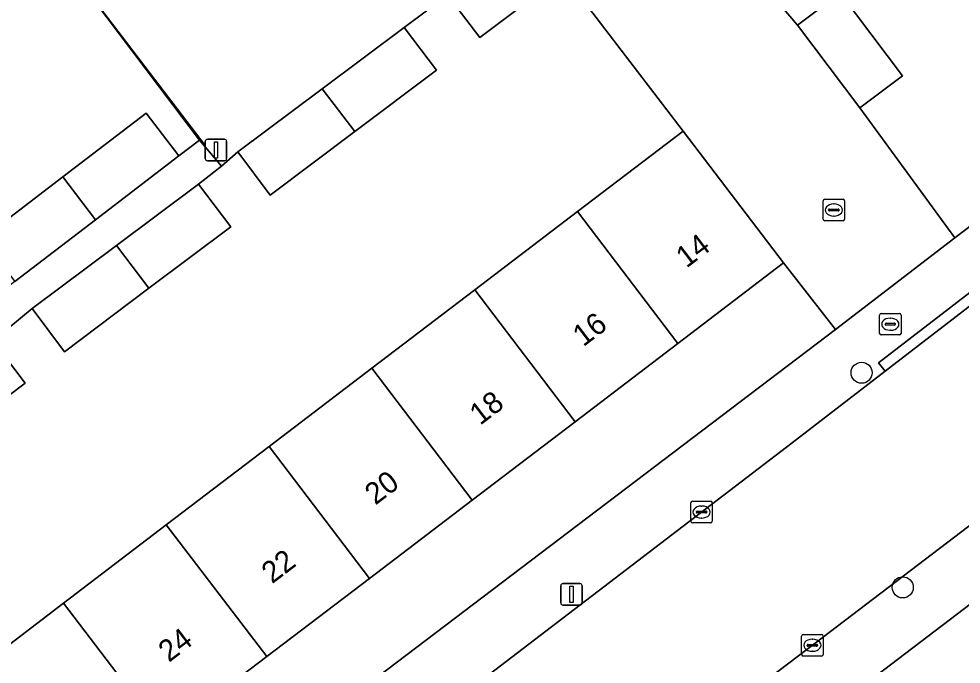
# Model space of a CAD drawing. Extents: x 160030 to 160839, y 385325 to 386450.
# Drawn here: x 160363.46 to 160407.21, y 385760.66 to 385790.62 of the extents above; entities that cross this region are included whole.
import ezdxf

# ---------------------------------------------------------------- set-up
doc = ezdxf.new("R2010")
doc.units = 0
for name, color, linetype in [('IMGEO_Boom', 7, 'Continuous'), ('IMGEO_Brandkraan', 7, 'Continuous'), ('IMGEO_Erf', 7, 'Continuous'), ('IMGEO_Kolk', 7, 'Continuous'), ('IMGEO_Lichtmast', 7, 'Continuous'), ('IMGEO_Muur', 7, 'Continuous'), ('IMGEO_Pand', 7, 'Continuous'), ('IMGEO_Pand_nummerreeks', 7, 'Continuous'), ('IMGEO_Rijbaan_lokaal_gesloten', 7, 'Continuous'), ('IMGEO_Rijbaan_lokaal_open', 7, 'Continuous'), ('IMGEO_Voetpad_open', 7, 'Continuous')]:
    doc.layers.add(name, color=color, linetype=linetype)

msp = doc.modelspace()

# ---------------------------------------------------------------- linework, layer by layer
at = {"layer": 'IMGEO_Boom'}
for centre in [(160402.589, 385774.189), (160404.501, 385764.222)]:
    msp.add_circle(centre, 0.489, dxfattribs=at)
at = {"layer": 'IMGEO_Brandkraan'}
for p, q in [((160403.423, 385776.017), (160403.423, 385776.869)), ((160403.498, 385776.943), (160404.35, 385776.943)), ((160403.911, 385776.723), (160403.936, 385776.723)), ((160404.424, 385776.869), (160404.424, 385776.017)), ((160403.682, 385776.437), (160403.682, 385776.449)), ((160404.12, 385776.4), (160403.722, 385776.4)), ((160403.725, 385776.486), (160404.123, 385776.486)), ((160404.166, 385776.449), (160404.166, 385776.437)), ((160404.35, 385775.943), (160403.498, 385775.943)), ((160403.934, 385776.163), (160403.909, 385776.163))]:
    msp.add_line(p, q, dxfattribs=at)
for points in [[(160403.423, 385776.017), (160403.423, 385776.869)], [(160403.498, 385776.943), (160404.35, 385776.943)], [(160404.424, 385776.869), (160404.424, 385776.017)], [(160404.35, 385775.943), (160403.498, 385775.943)]]:
    msp.add_lwpolyline(points, dxfattribs=at)
for centre, radius, start, end in [((160403.5, 385776.867), 0.0765, 91.552, 178.448), ((160403.5, 385776.867), 0.0765, 91.552, 178.448), ((160404.348, 385776.867), 0.0765, 1.552, 88.448), ((160404.348, 385776.867), 0.0765, 1.552, 88.448), ((160403.722, 385776.446), 0.0403, 85.8775, 175.7526), ((160403.719, 385776.436), 0.0366, 178.938, 274.7102), ((160404.123, 385776.443), 0.043, 264.8664, 352.4533), ((160404.127, 385776.448), 0.0386, 1.7309, 96.639), ((160403.5, 385776.019), 0.0765, 181.552, 268.448), ((160403.5, 385776.019), 0.0765, 181.552, 268.448), ((160404.348, 385776.019), 0.0765, 271.552, 358.448), ((160404.348, 385776.019), 0.0765, 271.552, 358.448)]:
    msp.add_arc(centre, radius, start, end, dxfattribs=at)
for centre, major_axis, ratio, start_param, end_param in [((160403.91, 385776.443), (-0.387, 0.002), 0.722429, 4.712389, 7.853982), ((160403.935, 385776.443), (-0.39, 0.002), 0.717154, 1.570796, 4.712389)]:
    msp.add_ellipse(centre, major_axis=major_axis, ratio=ratio, start_param=start_param, end_param=end_param, dxfattribs=at)
at = {"layer": 'IMGEO_Erf'}
for points in [[(160379.773, 385820.336), (160382.575, 385816.635), (160385.586, 385812.658), (160383.578, 385811.138), (160385.012, 385809.268), (160387.001, 385810.774), (160389.812, 385807.062), (160392.815, 385803.096), (160390.826, 385801.59), (160392.329, 385799.662), (160394.322, 385801.189), (160397.118, 385797.54), (160400.181, 385793.542), (160398.188, 385792.015), (160399.617, 385790.332), (160401.599, 385791.824), (160404.494, 385787.977), (160402.512, 385786.485), (160406.915, 385780.456), (160424.865, 385794.109)], [(160361.761, 385780.417), (160365.508, 385783.286), (160369.374, 385786.247), (160370.893, 385784.263), (160371.842, 385784.99), (160364.427, 385794.843), (160359.52, 385791.117)], [(160365.534, 385763.489), (160370.307, 385767.125), (160375.079, 385770.76), (160379.852, 385774.397), (160384.625, 385778.033), (160389.397, 385781.669), (160394.303, 385785.406), (160388.754, 385792.687), (160384.863, 385789.76), (160383.358, 385791.743), (160381.35, 385790.22), (160382.849, 385788.245), (160379.06, 385785.394), (160375.125, 385782.433), (160373.622, 385784.443), (160372.87, 385783.783), (160371.804, 385782.947), (160373.303, 385780.972), (160369.504, 385778.114), (160365.579, 385775.16), (160364.076, 385777.17), (160362.259, 385775.676), (160363.758, 385773.701), (160359.948, 385770.834)], [(160433.573, 385783.199), (160389.993, 385750), (160359.486, 385726.76)], [(160331.329, 385723.034), (160366.865, 385750), (160401.383, 385776.193), (160398.966, 385779.286), (160394.06, 385775.549), (160389.288, 385771.913), (160384.515, 385768.277), (160379.742, 385764.64), (160374.969, 385761.005), (160370.196, 385757.369), (160365.424, 385753.733), (160360.651, 385750.097)], [(160360.761, 385759.853), (160365.534, 385763.489)]]:
    msp.add_lwpolyline(points, dxfattribs=at)
at = {"layer": 'IMGEO_Kolk'}
for p, q in [((160400.801, 385781.32), (160400.801, 385782.172)), ((160400.876, 385782.246), (160401.728, 385782.246)), ((160401.289, 385782.026), (160401.314, 385782.026)), ((160401.802, 385782.172), (160401.802, 385781.32)), ((160401.06, 385781.74), (160401.06, 385781.752)), ((160401.498, 385781.703), (160401.1, 385781.703)), ((160401.103, 385781.789), (160401.501, 385781.789)), ((160401.544, 385781.752), (160401.544, 385781.74)), ((160401.728, 385781.246), (160400.876, 385781.246)), ((160401.312, 385781.466), (160401.287, 385781.466)), ((160394.658, 385767.293), (160394.658, 385768.145)), ((160394.733, 385768.219), (160395.585, 385768.219)), ((160395.146, 385767.999), (160395.171, 385767.999)), ((160395.659, 385768.145), (160395.659, 385767.293)), ((160394.917, 385767.713), (160394.917, 385767.725)), ((160395.355, 385767.676), (160394.957, 385767.676)), ((160394.96, 385767.762), (160395.358, 385767.762)), ((160395.401, 385767.725), (160395.401, 385767.713)), ((160395.585, 385767.219), (160394.733, 385767.219)), ((160395.169, 385767.439), (160395.144, 385767.439)), ((160399.806, 385761.106), (160399.806, 385761.958)), ((160399.881, 385762.032), (160400.733, 385762.032)), ((160400.807, 385761.958), (160400.807, 385761.106)), ((160400.065, 385761.526), (160400.065, 385761.538)), ((160400.503, 385761.489), (160400.105, 385761.489)), ((160400.108, 385761.575), (160400.506, 385761.575)), ((160400.294, 385761.812), (160400.319, 385761.812)), ((160400.549, 385761.538), (160400.549, 385761.526)), ((160400.733, 385761.032), (160399.881, 385761.032)), ((160400.317, 385761.252), (160400.292, 385761.252))]:
    msp.add_line(p, q, dxfattribs=at)
for points in [[(160400.801, 385781.32), (160400.801, 385782.172)], [(160400.876, 385782.246), (160401.728, 385782.246)], [(160401.802, 385782.172), (160401.802, 385781.32)], [(160401.728, 385781.246), (160400.876, 385781.246)], [(160394.658, 385767.293), (160394.658, 385768.145)], [(160394.733, 385768.219), (160395.585, 385768.219)], [(160395.659, 385768.145), (160395.659, 385767.293)], [(160395.585, 385767.219), (160394.733, 385767.219)], [(160399.806, 385761.106), (160399.806, 385761.958)], [(160399.881, 385762.032), (160400.733, 385762.032)], [(160400.807, 385761.958), (160400.807, 385761.106)], [(160400.733, 385761.032), (160399.881, 385761.032)]]:
    msp.add_lwpolyline(points, dxfattribs=at)
for centre, radius, start, end in [((160400.878, 385782.17), 0.0765, 91.552, 178.448), ((160400.878, 385782.17), 0.0765, 91.552, 178.448), ((160401.726, 385782.17), 0.0765, 1.552, 88.448), ((160401.726, 385782.17), 0.0765, 1.552, 88.448), ((160401.1, 385781.749), 0.0403, 85.8775, 175.7526), ((160401.097, 385781.739), 0.0366, 178.938, 274.7102), ((160401.501, 385781.746), 0.043, 264.8664, 352.4533), ((160401.505, 385781.751), 0.0386, 1.7309, 96.639), ((160400.878, 385781.322), 0.0765, 181.552, 268.448), ((160400.878, 385781.322), 0.0765, 181.552, 268.448), ((160401.726, 385781.322), 0.0765, 271.552, 358.448), ((160401.726, 385781.322), 0.0765, 271.552, 358.448), ((160394.735, 385768.143), 0.0765, 91.552, 178.448), ((160394.735, 385768.143), 0.0765, 91.552, 178.448), ((160395.583, 385768.143), 0.0765, 1.552, 88.448), ((160395.583, 385768.143), 0.0765, 1.552, 88.448), ((160394.957, 385767.722), 0.0403, 85.8775, 175.7526), ((160394.954, 385767.712), 0.0366, 178.938, 274.7102), ((160395.358, 385767.719), 0.043, 264.8664, 352.4533), ((160395.362, 385767.724), 0.0386, 1.7309, 96.639), ((160394.735, 385767.295), 0.0765, 181.552, 268.448), ((160394.735, 385767.295), 0.0765, 181.552, 268.448), ((160395.583, 385767.295), 0.0765, 271.552, 358.448), ((160395.583, 385767.295), 0.0765, 271.552, 358.448), ((160399.883, 385761.956), 0.0765, 91.552, 178.448), ((160399.883, 385761.956), 0.0765, 91.552, 178.448), ((160400.731, 385761.956), 0.0765, 1.552, 88.448), ((160400.731, 385761.956), 0.0765, 1.552, 88.448), ((160400.105, 385761.535), 0.0403, 85.8775, 175.7526), ((160400.102, 385761.525), 0.0366, 178.938, 274.7102), ((160400.506, 385761.532), 0.043, 264.8664, 352.4533), ((160400.51, 385761.537), 0.0386, 1.7309, 96.639), ((160399.883, 385761.108), 0.0765, 181.552, 268.448), ((160399.883, 385761.108), 0.0765, 181.552, 268.448), ((160400.731, 385761.108), 0.0765, 271.552, 358.448), ((160400.731, 385761.108), 0.0765, 271.552, 358.448)]:
    msp.add_arc(centre, radius, start, end, dxfattribs=at)
for centre, major_axis, ratio, start_param, end_param in [((160401.288, 385781.746), (-0.387, 0.002), 0.722429, 4.712389, 7.853982), ((160401.313, 385781.746), (-0.39, 0.002), 0.717154, 1.570796, 4.712389), ((160395.145, 385767.719), (-0.387, 0.002), 0.722429, 4.712389, 7.853982), ((160395.17, 385767.719), (-0.39, 0.002), 0.717154, 1.570796, 4.712389), ((160400.293, 385761.532), (-0.387, 0.002), 0.722429, 4.712389, 7.853982), ((160400.318, 385761.532), (-0.39, 0.002), 0.717154, 1.570796, 4.712389)]:
    msp.add_ellipse(centre, major_axis=major_axis, ratio=ratio, start_param=start_param, end_param=end_param, dxfattribs=at)
at = {"layer": 'IMGEO_Lichtmast'}
for p, q in [((160372.219, 385785.032), (160373.009, 385785.032)), ((160373.009, 385785.032), (160372.219, 385785.032)), ((160372.119, 385784.132), (160372.119, 385784.932)), ((160372.119, 385784.932), (160372.119, 385784.132)), ((160373.109, 385784.932), (160373.109, 385784.132)), ((160373.109, 385784.132), (160373.109, 385784.932)), ((160373.009, 385784.032), (160372.219, 385784.032)), ((160372.219, 385784.032), (160373.009, 385784.032)), ((160388.621, 385763.5), (160388.621, 385764.3)), ((160388.621, 385764.3), (160388.621, 385763.5)), ((160388.721, 385764.4), (160389.511, 385764.4)), ((160389.511, 385764.4), (160388.721, 385764.4)), ((160389.611, 385764.3), (160389.611, 385763.5)), ((160389.611, 385763.5), (160389.611, 385764.3)), ((160389.511, 385763.4), (160388.721, 385763.4)), ((160388.721, 385763.4), (160389.511, 385763.4))]:
    msp.add_line(p, q, dxfattribs=at)
for points in [[(160372.539, 385784.907), (160372.689, 385784.907), (160372.689, 385784.157), (160372.539, 385784.157), (160372.539, 385784.907)], [(160389.041, 385764.275), (160389.191, 385764.275), (160389.191, 385763.525), (160389.041, 385763.525), (160389.041, 385764.275)]]:
    msp.add_lwpolyline(points, dxfattribs=at)
for centre, start, end in [((160372.219, 385784.932), 90, 180), ((160372.219, 385784.932), 90, 180), ((160373.009, 385784.932), 0, 90), ((160373.009, 385784.932), 360, 90), ((160372.219, 385784.132), 180, 270), ((160372.219, 385784.132), 180, 270), ((160373.009, 385784.132), 270, 0), ((160373.009, 385784.132), 270, 0), ((160388.721, 385764.3), 90, 180), ((160388.721, 385764.3), 90, 180), ((160389.511, 385764.3), 0, 90), ((160389.511, 385764.3), 360, 90), ((160388.721, 385763.5), 180, 270), ((160388.721, 385763.5), 180, 270), ((160389.511, 385763.5), 270, 0), ((160389.511, 385763.5), 270, 0)]:
    msp.add_arc(centre, 0.1, start, end, dxfattribs=at)
at = {"layer": 'IMGEO_Muur'}
for points in [[(160372.133, 385784.749), (160364.427, 385794.843)], [(160388.754, 385792.687), (160394.303, 385785.406)]]:
    msp.add_lwpolyline(points, dxfattribs=at)
at = {"layer": 'IMGEO_Pand'}
for points in [[(160387.237, 385794.686), (160383.358, 385791.743), (160384.863, 385789.76), (160388.754, 385792.687)], [(160404.494, 385787.977), (160401.599, 385791.824), (160399.617, 385790.332), (160402.512, 385786.485)], [(160379.06, 385785.394), (160382.849, 385788.245), (160381.35, 385790.22), (160377.548, 385787.378)], [(160377.548, 385787.378), (160373.622, 385784.443), (160375.125, 385782.433), (160379.06, 385785.394)], [(160370.893, 385784.263), (160369.374, 385786.247), (160365.508, 385783.286), (160367.02, 385781.296)], [(160394.06, 385775.549), (160398.966, 385779.286), (160394.303, 385785.406), (160389.397, 385781.669)], [(160367.02, 385781.296), (160365.508, 385783.286), (160361.761, 385780.417), (160363.281, 385778.432)], [(160369.504, 385778.114), (160373.303, 385780.972), (160371.804, 385782.947), (160367.993, 385780.098)], [(160389.397, 385781.669), (160384.625, 385778.033), (160389.288, 385771.913), (160394.06, 385775.549)], [(160367.993, 385780.098), (160364.076, 385777.17), (160365.579, 385775.16), (160369.504, 385778.114)], [(160384.625, 385778.033), (160379.852, 385774.397), (160384.515, 385768.277), (160389.288, 385771.913)], [(160359.948, 385770.834), (160363.758, 385773.701), (160362.259, 385775.676), (160358.436, 385772.818)], [(160379.742, 385764.64), (160384.515, 385768.277), (160379.852, 385774.397), (160375.079, 385770.76)], [(160375.079, 385770.76), (160370.307, 385767.125), (160374.969, 385761.005), (160379.742, 385764.64)], [(160370.196, 385757.369), (160374.969, 385761.005), (160370.307, 385767.125), (160365.534, 385763.489)], [(160365.534, 385763.489), (160360.761, 385759.853), (160365.424, 385753.733), (160370.196, 385757.369)]]:
    msp.add_lwpolyline(points, close=True, dxfattribs=at)
at = {"layer": 'IMGEO_Rijbaan_lokaal_gesloten'}
msp.add_lwpolyline([(160337.484, 385713.901), (160342.671, 385717.746), (160354.26, 385726.531), (160358.201, 385729.526), (160385.133, 385750), (160400.437, 385761.634), (160420.803, 385777.146), (160430.014, 385784.168), (160425.32, 385790.614), (160412.341, 385780.93), (160408.525, 385777.99), (160403.685, 385774.26), (160399.366, 385770.932), (160380.496, 385756.509), (160371.922, 385750), (160352.828, 385735.505), (160337.658, 385723.913), (160332.826, 385720.277)], dxfattribs=at)
at = {"layer": 'IMGEO_Rijbaan_lokaal_open'}
for points in [[(160364.427, 385794.843), (160371.842, 385784.99), (160372.87, 385783.783), (160373.622, 385784.443), (160377.548, 385787.378), (160381.35, 385790.22), (160383.358, 385791.743)], [(160388.754, 385792.687), (160394.303, 385785.406), (160398.966, 385779.286), (160401.383, 385776.193), (160406.915, 385780.456), (160402.512, 385786.485), (160399.617, 385790.332), (160398.188, 385792.015)]]:
    msp.add_lwpolyline(points, dxfattribs=at)
at = {"layer": 'IMGEO_Voetpad_open'}
for points in [[(160429.698, 385796.484), (160424.865, 385794.109), (160406.915, 385780.456), (160401.383, 385776.193), (160366.865, 385750), (160331.329, 385723.034)], [(160399.366, 385770.932), (160403.685, 385774.26), (160403.38, 385774.656), (160408.22, 385778.386), (160408.525, 385777.99), (160412.341, 385780.93), (160425.32, 385790.614), (160427.919, 385792.615)], [(160432.998, 385786.381), (160432.128, 385785.779), (160430.014, 385784.168), (160420.803, 385777.146), (160400.437, 385761.634), (160385.133, 385750), (160358.201, 385729.526), (160358.503, 385729.128), (160354.562, 385726.133), (160354.26, 385726.531), (160342.671, 385717.746), (160337.484, 385713.901), (160339.266, 385710.826)], [(160339.818, 385711.772), (160357.171, 385724.957), (160359.486, 385726.76), (160389.993, 385750), (160433.573, 385783.199)], [(160330.265, 385722.757), (160332.826, 385720.277), (160337.658, 385723.913), (160352.828, 385735.505), (160371.922, 385750), (160380.496, 385756.509), (160399.366, 385770.932)]]:
    msp.add_lwpolyline(points, dxfattribs=at)
for points in [[(160364.076, 385777.17), (160367.993, 385780.098), (160371.804, 385782.947), (160372.87, 385783.783), (160371.842, 385784.99), (160370.893, 385784.263), (160367.02, 385781.296), (160363.281, 385778.432), (160361.367, 385776.965), (160357.482, 385773.99), (160353.754, 385771.134), (160351.792, 385769.618), (160352.243, 385769.023), (160352.695, 385768.427), (160354.531, 385769.899), (160358.436, 385772.818), (160362.259, 385775.676)], [(160408.525, 385777.99), (160408.22, 385778.386), (160403.38, 385774.656), (160403.685, 385774.26)]]:
    msp.add_lwpolyline(points, close=True, dxfattribs=at)

# ---------------------------------------------------------------- texts
at = {"layer": 'IMGEO_Pand_nummerreeks'}
for s, p in [('14', (160394.459, 385779.02)), ('16', (160389.667, 385775.369)), ('18', (160384.878, 385771.721)), ('20', (160380.014, 385768.016)), ('22', (160375.218, 385764.361)), ('24', (160370.428, 385760.713))]:
    msp.add_text(s, height=1, rotation=37.3012, dxfattribs=at).set_placement(p)

doc.saveas('drawing.dxf')
